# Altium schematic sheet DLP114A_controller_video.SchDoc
size 558 x 431 mm; Date: Not shown in title block; ApprovedBy: Not shown in title block; CheckedBy: Not shown in title block; Author: Not shown in title block; CompanyName: Not shown in title block; Engineer: Not shown in title block; Organization: Not shown in title block; Address1: Not shown in title block; Address2: Not shown in title block; Address3: Not shown in title block; Address4: Not shown in title block; DocumentNumber: 5; Revision: Use project parameter SCH_Rev; SheetNumber: 5; SheetTotal: 7; PageSetup: Record=PageOptions¦CenterHorizontal=True¦CenterVertical=True¦PrintScale=1.00¦XCorrection=1.00¦YCorrection=1.00¦PrintKind=0¦BorderSize=5000000¦LeftOffset=0¦BottomOffset=0¦Orientation=2¦PaperLength=1000¦PaperWidth=1000¦Scale=100¦PaperSource=15¦PrintQuality=600¦MediaType=1¦DitherType=10¦PaperKind=Letter¦PrintScaleMode=1
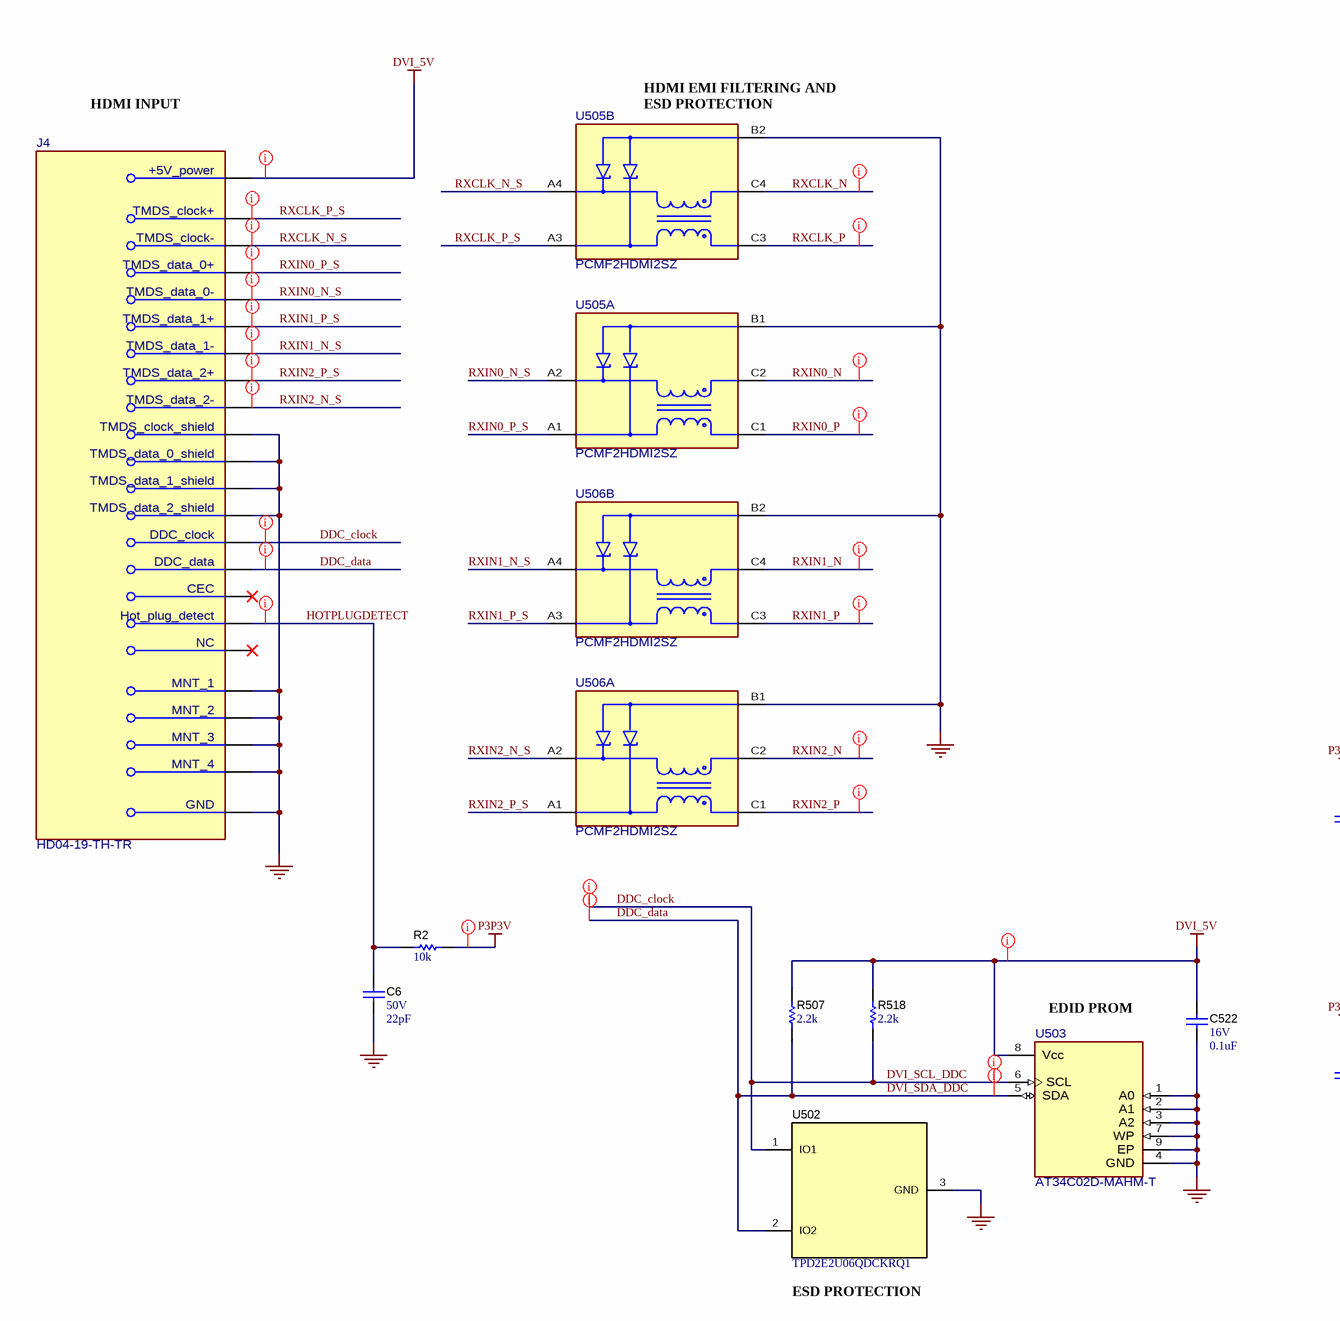
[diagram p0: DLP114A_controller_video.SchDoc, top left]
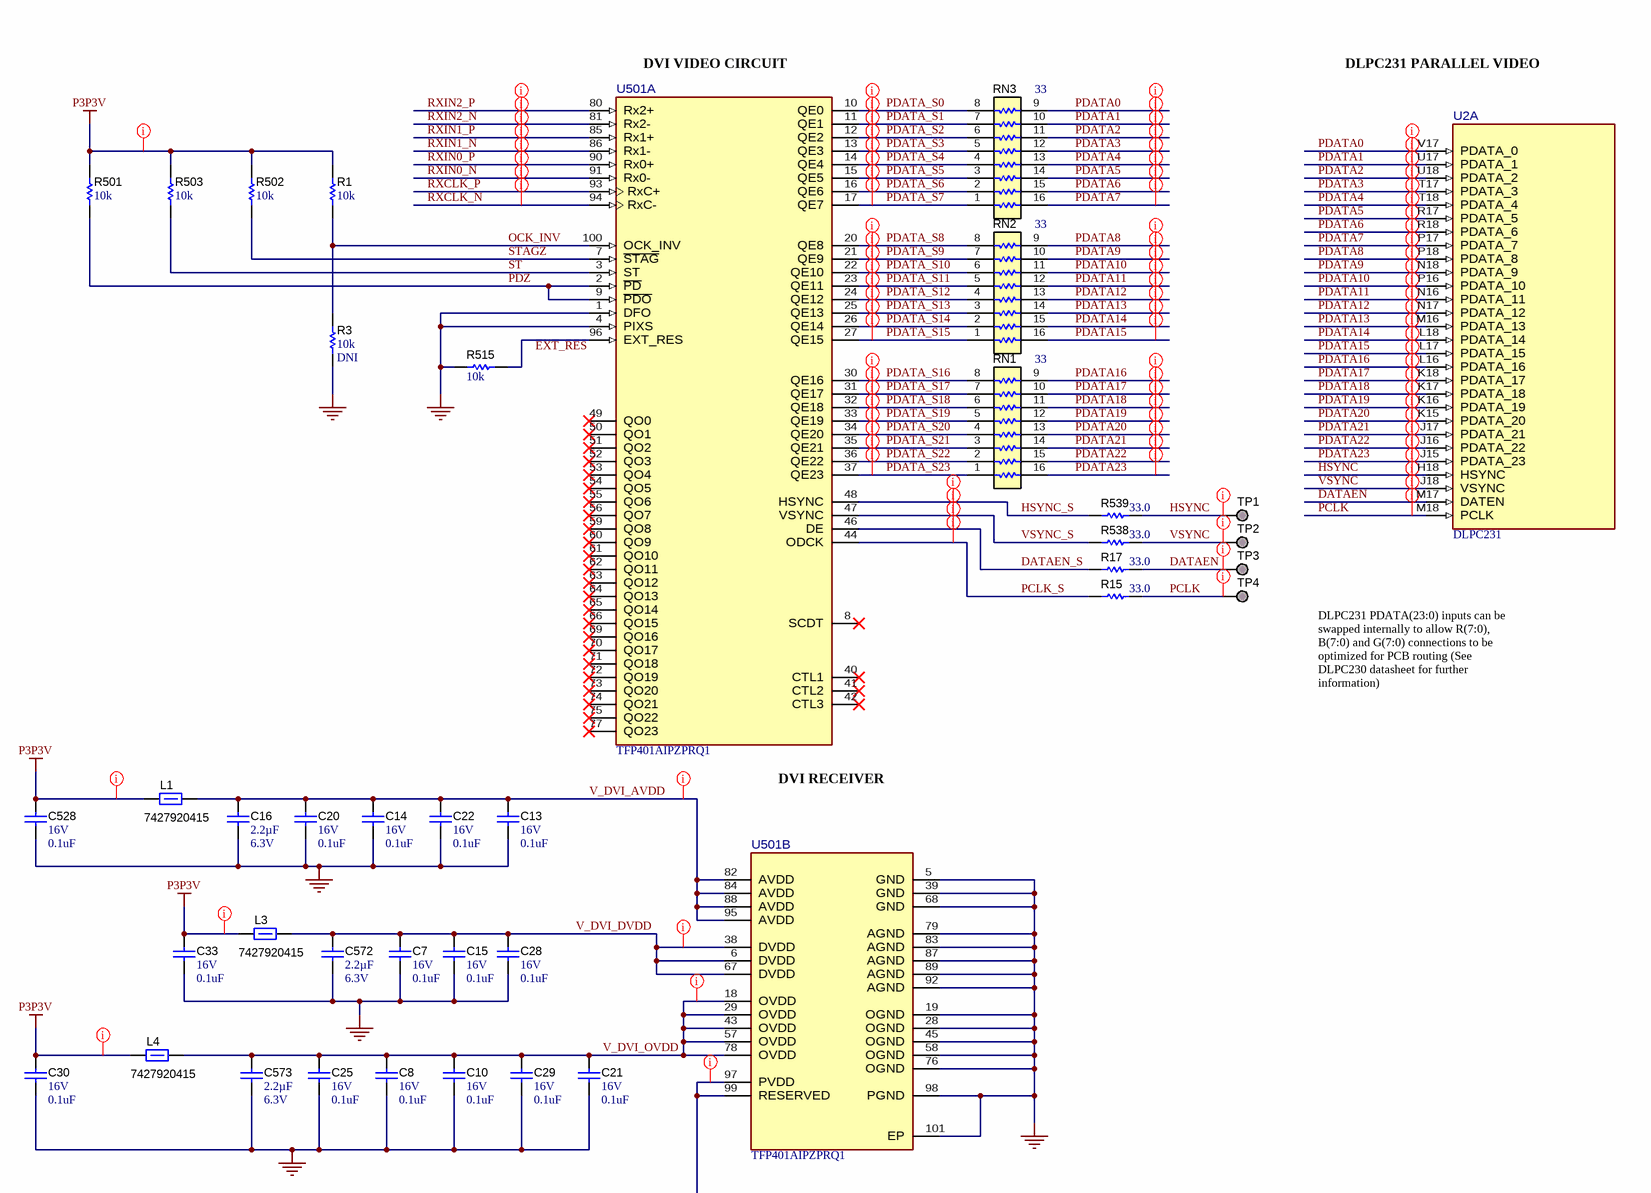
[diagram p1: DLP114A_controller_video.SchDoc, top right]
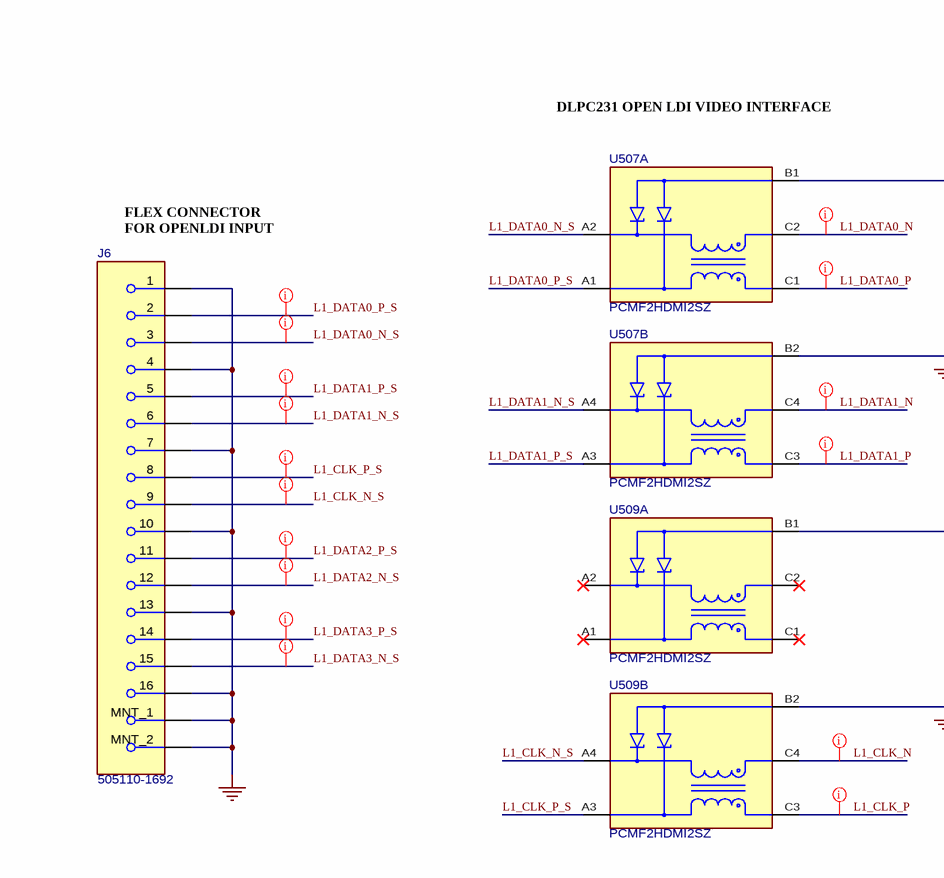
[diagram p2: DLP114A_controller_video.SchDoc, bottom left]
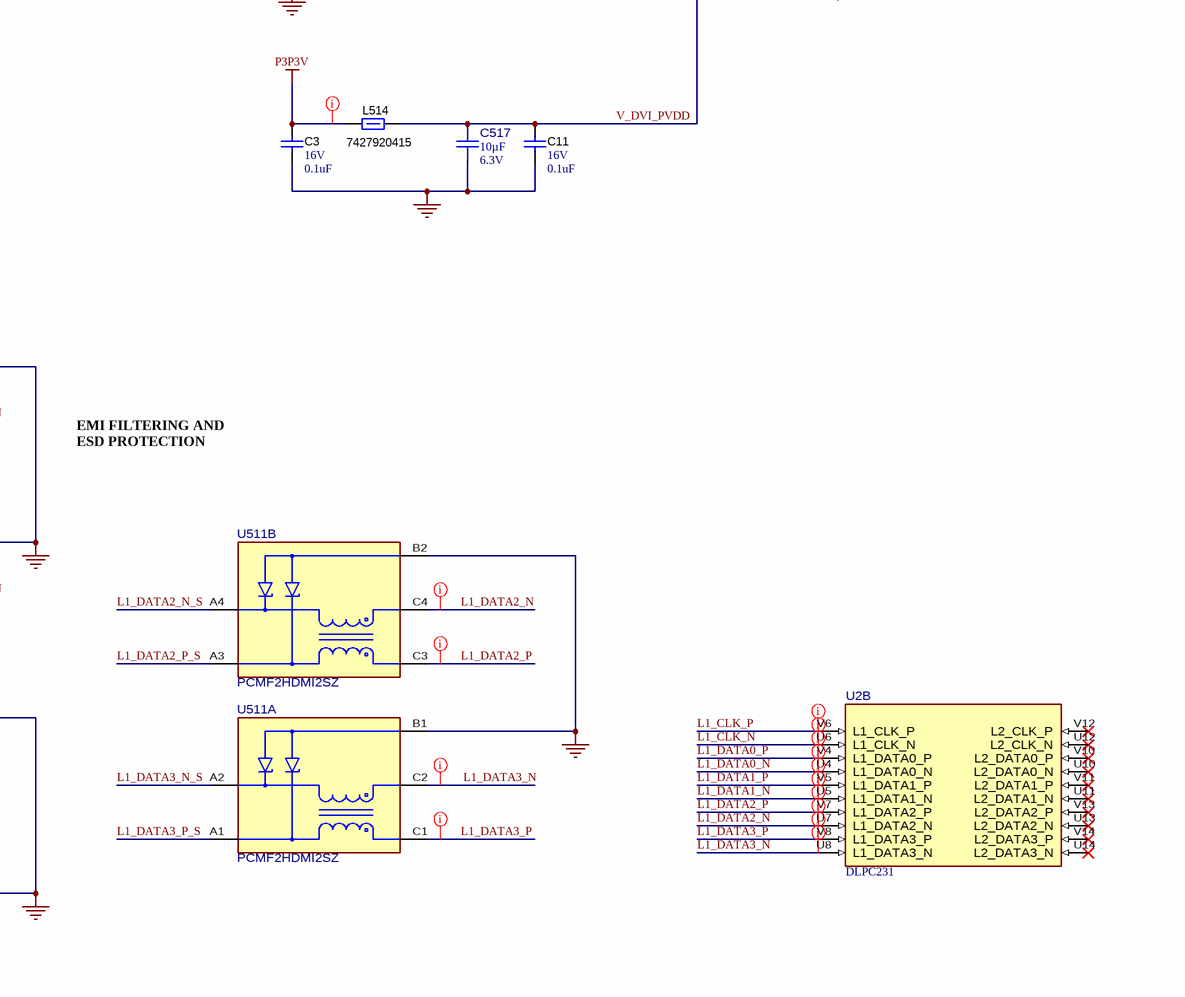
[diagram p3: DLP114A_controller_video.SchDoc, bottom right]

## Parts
C3  VDC_V: 16V  ValueDisplayed: 0.1uF  [0402]  (hidden comment: GCM155R71C104KA55D)
C6  VDC_V: 50V  ValueDisplayed: 22pF  [0402]  (hidden comment: CL05C220JB5NNNC)
C7  VDC_V: 16V  ValueDisplayed: 0.1uF  [0402]  (hidden comment: GCM155R71C104KA55D)
C8  VDC_V: 16V  ValueDisplayed: 0.1uF  [0402]  (hidden comment: GCM155R71C104KA55D)
C10  VDC_V: 16V  ValueDisplayed: 0.1uF  [0402]  (hidden comment: GCM155R71C104KA55D)
C11  VDC_V: 16V  ValueDisplayed: 0.1uF  [0402]  (hidden comment: GCM155R71C104KA55D)
C13  VDC_V: 16V  ValueDisplayed: 0.1uF  [0402]  (hidden comment: GCM155R71C104KA55D)
C14  VDC_V: 16V  ValueDisplayed: 0.1uF  [0402]  (hidden comment: GCM155R71C104KA55D)
C15  VDC_V: 16V  ValueDisplayed: 0.1uF  [0402]  (hidden comment: GCM155R71C104KA55D)
C16  Cap_F: 2.2µF  VDC_V: 6.3V  [0603]  (hidden comment: GCM188R70J225KE22D)
C20  VDC_V: 16V  ValueDisplayed: 0.1uF  [0402]  (hidden comment: GCM155R71C104KA55D)
C21  VDC_V: 16V  ValueDisplayed: 0.1uF  [0402]  (hidden comment: GCM155R71C104KA55D)
C22  VDC_V: 16V  ValueDisplayed: 0.1uF  [0402]  (hidden comment: GCM155R71C104KA55D)
C25  VDC_V: 16V  ValueDisplayed: 0.1uF  [0402]  (hidden comment: GCM155R71C104KA55D)
C28  VDC_V: 16V  ValueDisplayed: 0.1uF  [0402]  (hidden comment: GCM155R71C104KA55D)
C29  VDC_V: 16V  ValueDisplayed: 0.1uF  [0402]  (hidden comment: GCM155R71C104KA55D)
C30  VDC_V: 16V  ValueDisplayed: 0.1uF  [0402]  (hidden comment: GCM155R71C104KA55D)
C33  VDC_V: 16V  ValueDisplayed: 0.1uF  [0402]  (hidden comment: GCM155R71C104KA55D)
C517  Cap_F: 10µF  VDC_V: 6.3V  [FP-CGA4J1X7R0J106K125AC_0805-MFG]  (hidden comment: CGA4J1X7R0J106K125AC)
C522  VDC_V: 16V  ValueDisplayed: 0.1uF  [0402]  (hidden comment: GCM155R71C104KA55D)
C528  VDC_V: 16V  ValueDisplayed: 0.1uF  [0402]  (hidden comment: GCM155R71C104KA55D)
C572  Cap_F: 2.2µF  VDC_V: 6.3V  [0603]  (hidden comment: GCM188R70J225KE22D)
C573  Cap_F: 2.2µF  VDC_V: 6.3V  [0603]  (hidden comment: GCM188R70J225KE22D)
J4  HD04-19-TH-TR  [FP-HD04-19-TH-TR_CONN_HDMI_RCPT19-MFG]
J6  505110-1692  [FP-505110-1692_CONN_SMT_12MM7_5MM25-MFG]
L1  7427920415  [0805_HV]
L3  7427920415  [0805_HV]
L4  7427920415  [0805_HV]
L514  7427920415  [0805_HV]
R1  ValueDisplayed: 10k  [0402]  (hidden comment: ERJ-2GEJ103X)
R2  ValueDisplayed: 10k  [0402]  (hidden comment: ERJ-2GEJ103X)
R3  ValueDisplayed: 10k  Parameter 1: DNI  [0402]  (hidden comment: ERJ-2GEJ103X)
R15  ValueDisplayed: 33.0  [0402]  (hidden comment: ERJ-2RKF33R0X)
R17  ValueDisplayed: 33.0  [0402]  (hidden comment: ERJ-2RKF33R0X)
R501  ValueDisplayed: 10k  [0402]  (hidden comment: ERJ-2GEJ103X)
R502  ValueDisplayed: 10k  [0402]  (hidden comment: ERJ-2GEJ103X)
R503  ValueDisplayed: 10k  [0402]  (hidden comment: ERJ-2GEJ103X)
R507  ValueDisplayed: 2.2k  [0402]  (hidden comment: CRCW04022K20JNED)
R515  ValueDisplayed: 10k  [0402]  (hidden comment: ERJ-2GEJ103X)
R518  ValueDisplayed: 2.2k  [0402]  (hidden comment: CRCW04022K20JNED)
R538  ValueDisplayed: 33.0  [0402]  (hidden comment: ERJ-2RKF33R0X)
R539  ValueDisplayed: 33.0  [0402]  (hidden comment: ERJ-2RKF33R0X)
RN1  ValueDisplayed: 33  [RESCAXS_EXB-2HV]  (hidden comment: EXB-2HV330JV)
RN2  ValueDisplayed: 33  [RESCAXS_EXB-2HV]  (hidden comment: EXB-2HV330JV)
RN3  ValueDisplayed: 33  [RESCAXS_EXB-2HV]  (hidden comment: EXB-2HV330JV)
TP1  TESTPOINT  [TESTPOINT]  (value not drawn)  (no BOM)
TP2  TESTPOINT  [TESTPOINT]  (value not drawn)  (no BOM)
TP3  TESTPOINT  [TESTPOINT]  (value not drawn)  (no BOM)
TP4  TESTPOINT  [TESTPOINT]  (value not drawn)  (no BOM)
U2  DLPC231  [ZEK0324A-MFG]  (parts A,B of 9)
U501  TFP401AIPZPRQ1  [PZP0100H-MFG]  (parts A,B of 2)
U502  TPD2E2U06QDCKRQ1  [DCK0003A_N]
U503  AT34C02D-MAHM-T  [FP-AT34C02D-MAHM-T_UDFN8-MFG]
U505  PCMF2HDMI2SZ  [FP-PCMF2HDMI2SZ_WLCSP10-MFG]  (parts A,B of 2)
U506  PCMF2HDMI2SZ  [FP-PCMF2HDMI2SZ_WLCSP10-MFG]  (parts A,B of 2)
U507  PCMF2HDMI2SZ  [FP-PCMF2HDMI2SZ_WLCSP10-MFG]  (parts A,B of 2)
U509  PCMF2HDMI2SZ  [FP-PCMF2HDMI2SZ_WLCSP10-MFG]  (parts A,B of 2)
U511  PCMF2HDMI2SZ  [FP-PCMF2HDMI2SZ_WLCSP10-MFG]  (parts A,B of 2)

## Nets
DVI_5V: C522.1 J4.18(+5V_power) R507.2 R518.2 U503.8(Vcc)
GND: C3.2 C6.2 C7.2 C8.2 C10.2 C11.2 C13.2 C14.2 C15.2 C16.2 C20.2 C21.2 C22.2 C25.2 C28.2 C29.2 C30.2 C33.2 C517.1 C522.2 C528.2 C572.2 C573.2 J4.2(TMDS_data_2_shield) J4.5(TMDS_data_1_shield) J4.8(TMDS_data_0_shield) J4.11(TMDS_clock_shield) J4.17(GND) J4.20(MNT_1) J4.21(MNT_2) J4.22(MNT_3) J4.23(MNT_4) J6.1 J6.4 J6.7 J6.10 J6.13 J6.16 J6.17(MNT_1) J6.18(MNT_2) R3.1 R515.2 U501.1(DFO) U501.4(PIXS) U501.5(GND) U501.19(OGND) U501.28(OGND) U501.39(GND) U501.45(OGND) U501.58(OGND) U501.68(GND) U501.76(OGND) U501.79(AGND) U501.83(AGND) U501.87(AGND) U501.89(AGND) U501.92(AGND) U501.98(PGND) U501.101(EP) U502.3(GND) U503.1(A0) U503.2(A1) U503.3(A2) U503.4(GND) U503.7(WP) U503.9(EP) U505.B1(GND_CH1) U505.B2(GND_CH2) U506.B1(GND_CH1) U506.B2(GND_CH2) U507.B1(GND_CH1) U507.B2(GND_CH2) U509.B1(GND_CH1) U509.B2(GND_CH2) U511.B1(GND_CH1) U511.B2(GND_CH2)
P3P3V: C3.1 C30.1 C33.1 C528.1 L1.1 L3.1 L4.1 L514.1 R1.2 R2.2 R501.2 R502.2 R503.2
DATAEN: R17.2 TP3.1 U2.M17(DATEN)
DATAEN_S: R17.1 U501.46(DE)
DDC_clock: J4.15(DDC_clock) R518.1 U502.1(IO1) U503.6(SCL)  [also labelled DVI_SCL_DDC]
DDC_data: J4.16(DDC_data) R507.1 U502.2(IO2) U503.5(SDA)  [also labelled DVI_SDA_DDC]
HOTPLUGDETECT: C6.1 J4.19(Hot_plug_detect) R2.1
HSYNC: R539.2 TP1.1 U2.H18(HSYNC)
HSYNC_S: R539.1 U501.48(HSYNC)
L1_CLK_N: U2.U6(L1_CLK_N) U509.C4(CH2_OUT-)
L1_CLK_N_S: J6.9 U509.A4(CH2_IN-)
L1_CLK_P: U2.V6(L1_CLK_P) U509.C3(CH2_OUT+)
L1_CLK_P_S: J6.8 U509.A3(CH2_IN+)
L1_DATA0_N: U2.U4(L1_DATA0_N) U507.C2(CH1_OUT-)
L1_DATA0_N_S: J6.3 U507.A2(CH1_IN-)
L1_DATA0_P: U2.V4(L1_DATA0_P) U507.C1(CH1_OUT+)
L1_DATA0_P_S: J6.2 U507.A1(CH1_IN+)
L1_DATA1_N: U2.U5(L1_DATA1_N) U507.C4(CH2_OUT-)
L1_DATA1_N_S: J6.6 U507.A4(CH2_IN-)
L1_DATA1_P: U2.V5(L1_DATA1_P) U507.C3(CH2_OUT+)
L1_DATA1_P_S: J6.5 U507.A3(CH2_IN+)
L1_DATA2_N: U2.U7(L1_DATA2_N) U511.C4(CH2_OUT-)
L1_DATA2_N_S: J6.12 U511.A4(CH2_IN-)
L1_DATA2_P: U2.V7(L1_DATA2_P) U511.C3(CH2_OUT+)
L1_DATA2_P_S: J6.11 U511.A3(CH2_IN+)
L1_DATA3_N: U2.U8(L1_DATA3_N) U511.C2(CH1_OUT-)
L1_DATA3_N_S: J6.15 U511.A2(CH1_IN-)
L1_DATA3_P: U2.V8(L1_DATA3_P) U511.C1(CH1_OUT+)
L1_DATA3_P_S: J6.14 U511.A1(CH1_IN+)
OCK_INV: R1.1 R3.2 U501.100(OCK_INV)
PCLK: R15.2 TP4.1 U2.M18(PCLK)
PCLK_S: R15.1 U501.44(ODCK)
PDATA0: RN3.9 U2.V17(PDATA_0)
PDATA1: RN3.10 U2.U17(PDATA_1)
PDATA2: RN3.11 U2.U18(PDATA_2)
PDATA3: RN3.12 U2.T17(PDATA_3)
PDATA4: RN3.13 U2.T18(PDATA_4)
PDATA5: RN3.14 U2.R17(PDATA_5)
PDATA6: RN3.15 U2.R18(PDATA_6)
PDATA7: RN3.16 U2.P17(PDATA_7)
PDATA8: RN2.9 U2.P18(PDATA_8)
PDATA9: RN2.10 U2.N18(PDATA_9)
PDATA10: RN2.11 U2.P16(PDATA_10)
PDATA11: RN2.12 U2.N16(PDATA_11)
PDATA12: RN2.13 U2.N17(PDATA_12)
PDATA13: RN2.14 U2.M16(PDATA_13)
PDATA14: RN2.15 U2.L18(PDATA_14)
PDATA15: RN2.16 U2.L17(PDATA_15)
PDATA16: RN1.9 U2.L16(PDATA_16)
PDATA17: RN1.10 U2.K18(PDATA_17)
PDATA18: RN1.11 U2.K17(PDATA_18)
PDATA19: RN1.12 U2.K16(PDATA_19)
PDATA20: RN1.13 U2.K15(PDATA_20)
PDATA21: RN1.14 U2.J17(PDATA_21)
PDATA22: RN1.15 U2.J16(PDATA_22)
PDATA23: RN1.16 U2.J15(PDATA_23)
PDATA_S0: RN3.8 U501.10(QE0)
PDATA_S1: RN3.7 U501.11(QE1)
PDATA_S2: RN3.6 U501.12(QE2)
PDATA_S3: RN3.5 U501.13(QE3)
PDATA_S4: RN3.4 U501.14(QE4)
PDATA_S5: RN3.3 U501.15(QE5)
PDATA_S6: RN3.2 U501.16(QE6)
PDATA_S7: RN3.1 U501.17(QE7)
PDATA_S8: RN2.8 U501.20(QE8)
PDATA_S9: RN2.7 U501.21(QE9)
PDATA_S10: RN2.6 U501.22(QE10)
PDATA_S11: RN2.5 U501.23(QE11)
PDATA_S12: RN2.4 U501.24(QE12)
PDATA_S13: RN2.3 U501.25(QE13)
PDATA_S14: RN2.2 U501.26(QE14)
PDATA_S15: RN2.1 U501.27(QE15)
PDATA_S16: RN1.8 U501.30(QE16)
PDATA_S17: RN1.7 U501.31(QE17)
PDATA_S18: RN1.6 U501.32(QE18)
PDATA_S19: RN1.5 U501.33(QE19)
PDATA_S20: RN1.4 U501.34(QE20)
PDATA_S21: RN1.3 U501.35(QE21)
PDATA_S22: RN1.2 U501.36(QE22)
PDATA_S23: RN1.1 U501.37(QE23)
PDZ: R501.1 U501.2(~{PD}) U501.9(~{PDO})
RXCLK_N: U501.94(RxC-) U505.C4(CH2_OUT-)
RXCLK_N_S: J4.12(TMDS_clock-) U505.A4(CH2_IN-)
RXCLK_P: U501.93(RxC+) U505.C3(CH2_OUT+)
RXCLK_P_S: J4.10(TMDS_clock+) U505.A3(CH2_IN+)
RXIN0_N: U501.91(Rx0-) U505.C2(CH1_OUT-)
RXIN0_N_S: J4.9(TMDS_data_0-) U505.A2(CH1_IN-)
RXIN0_P: U501.90(Rx0+) U505.C1(CH1_OUT+)
RXIN0_P_S: J4.7(TMDS_data_0+) U505.A1(CH1_IN+)
RXIN1_N: U501.86(Rx1-) U506.C4(CH2_OUT-)
RXIN1_N_S: J4.6(TMDS_data_1-) U506.A4(CH2_IN-)
RXIN1_P: U501.85(Rx1+) U506.C3(CH2_OUT+)
RXIN1_P_S: J4.4(TMDS_data_1+) U506.A3(CH2_IN+)
RXIN2_N: U501.81(Rx2-) U506.C2(CH1_OUT-)
RXIN2_N_S: J4.3(TMDS_data_2-) U506.A2(CH1_IN-)
RXIN2_P: U501.80(Rx2+) U506.C1(CH1_OUT+)
RXIN2_P_S: J4.1(TMDS_data_2+) U506.A1(CH1_IN+)
ST: R503.1 U501.3(ST)
STAGZ: R502.1 U501.7(~{STAG})
V_DVI_AVDD: C13.1 C14.1 C16.1 C20.1 C22.1 L1.2 U501.82(AVDD) U501.84(AVDD) U501.88(AVDD) U501.95(AVDD)
V_DVI_DVDD: C7.1 C15.1 C28.1 C572.1 L3.2 U501.6(DVDD) U501.38(DVDD) U501.67(DVDD)
V_DVI_OVDD: C8.1 C10.1 C21.1 C25.1 C29.1 C573.1 L4.2 U501.18(OVDD) U501.29(OVDD) U501.43(OVDD) U501.57(OVDD) U501.78(OVDD)
V_DVI_PVDD: C11.1 C517.2 L514.2 U501.97(PVDD) U501.99(RESERVED)
VSYNC: R538.2 TP2.1 U2.J18(VSYNC)
VSYNC_S: R538.1 U501.47(VSYNC)
NetR515_1: R515.1 U501.96(EXT_RES)

Not connected (* = marked no-connect by the designer): J4 13(CEC)* 14(NC)*; U2 U10(L2_DATA0_N)* U11(L2_DATA1_N)* U12(L2_CLK_N)* U13(L2_DATA2_N)* U14(L2_DATA3_N)* V10(L2_DATA0_P)* V11(L2_DATA1_P)* V12(L2_CLK_P)* V13(L2_DATA2_P)* V14(L2_DATA3_P)*; U501 8(SCDT)* 40(CTL1)* 41(CTL2)* 42(CTL3)* 49(QO0)* 50(QO1)* 51(QO2)* 52(QO3)* 53(QO4)* 54(QO5)* 55(QO6)* 56(QO7)* 59(QO8)* 60(QO9)* 61(QO10)* 62(QO11)* 63(QO12)* 64(QO13)* 65(QO14)* 66(QO15)* 69(QO16)* 70(QO17)* 71(QO18)* 72(QO19)* 73(QO20)* 74(QO21)* 75(QO22)* 77(QO23)*; U509 A1(CH1_IN+)* A2(CH1_IN-)* C1(CH1_OUT+)* C2(CH1_OUT-)*

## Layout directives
net class 100 OHM (HDMI Signals): RXCLK_N, RXCLK_N_S, RXCLK_P, RXCLK_P_S, RXIN0_N, RXIN0_N_S, RXIN0_P, RXIN0_P_S, RXIN1_N, RXIN1_N_S, RXIN1_P, RXIN1_P_S, RXIN2_N, RXIN2_N_S, RXIN2_P, RXIN2_P_S
net class 50OHM: DATAEN, DATAEN_S, DDC_clock, DDC_data, HOTPLUGDETECT, HSYNC, HSYNC_S, L1_CLK_N, L1_CLK_P, L1_DATA0_N, L1_DATA0_P, L1_DATA1_N, L1_DATA1_P, L1_DATA2_N, L1_DATA2_P, L1_DATA3_N, L1_DATA3_P, PCLK, PCLK_S, PDATA0, PDATA1, PDATA2, PDATA3, PDATA4, PDATA5, PDATA6, PDATA7, PDATA8, PDATA9, PDATA10, PDATA11, PDATA12, PDATA13, PDATA14, PDATA15, PDATA16, PDATA17, PDATA18, PDATA19, PDATA20, PDATA21, PDATA22, PDATA23, PDATA_S0, PDATA_S1, PDATA_S2, PDATA_S3, PDATA_S4, PDATA_S5, PDATA_S6, PDATA_S7, PDATA_S8, PDATA_S9, PDATA_S10, PDATA_S11, PDATA_S12, PDATA_S13, PDATA_S14, PDATA_S15, PDATA_S16, PDATA_S17, PDATA_S18, PDATA_S19, PDATA_S20, PDATA_S21, PDATA_S22, PDATA_S23, VSYNC, VSYNC_S
net class 100 OHM (Open LDI): L1_CLK_N, L1_CLK_N_S, L1_CLK_P, L1_CLK_P_S, L1_DATA0_N, L1_DATA0_N_S, L1_DATA0_P, L1_DATA0_P_S, L1_DATA1_N, L1_DATA1_N_S, L1_DATA1_P, L1_DATA1_P_S, L1_DATA2_N, L1_DATA2_N_S, L1_DATA2_P, L1_DATA2_P_S, L1_DATA3_N, L1_DATA3_N_S, L1_DATA3_P, L1_DATA3_P_S
net class POWER: DVI_5V, P3P3V, V_DVI_AVDD, V_DVI_DVDD, V_DVI_OVDD, V_DVI_PVDD

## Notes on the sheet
- HDMI INPUT
- (near U505) HDMI EMI FILTERING AND
  ESD PROTECTION
- (near U501) DVI VIDEO CIRCUIT
- DLPC231 PARALLEL VIDEO INTERFACE
- DLPC231 PDATA(23:0) inputs can be
  swapped internally to allow R(7:0),
  B(7:0) and G(7:0) connections to be
  optimized for PCB routing (See
  DLPC230 datasheet for further
  information)
- (near U501) DVI RECEIVER
- EDID PROM
- (near U502) ESD PROTECTION
- DLPC231 OPEN LDI VIDEO INTERFACE
- FLEX CONNECTOR
  FOR OPENLDI INPUT
- EMI FILTERING AND
  ESD PROTECTION
- Labels drawn without touching a wire or pin: EXT_RES

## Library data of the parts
C3 C7 C8 C10 C11 C13-C15 C20-C22 C25 C28-C30 C33 C522 C528 = CMP-0006351-2: CAP, CERM, 0.1 uF, 16 V, +/- 10%, X7R, 0402; Manufacturer: MuRata; TaMin_C: -55°C; Polarized: N; SizeAreaWB_mm2: 3; Value1: Unknown; U/M: EA; Value: 0.1uF; TaMax_C: 125°C; SizeZ_mm: 0.6; SizeX_mm: 1; SizeY_mm: 0.5; Cap_F: 100nF; AEC Category: Q200
C6 = CMP-0085851-1: CAP, CERM, 22 pF, 50 V,+/- 5%, C0G/NP0, 0402; Manufacturer: Walsin; AEC Qualified: N; TaMax_C: 125°C; SizeX_mm: 1; Value: 22pF; SizeZ_mm: 0.6; AEC Category: Q200; TaMin_C: -55°C; SizeArea_mm2: 0.5; SizeAreaWB_mm2: 3; U/M: EA
C16 C572 C573 = CMP-0007134-5: CAP, CERM, 2.2 uF, 6.3 V, +/- 10%, X7R, AEC-Q200 Grade 1, 0603; Manufacturer: MuRata; TaMin_C: -55°C; Polarized: N; SizeAreaWB_mm2: 4.68; Value1: Unknown; U/M: EA; Value: 2.2uF; TaMax_C: 125°C; SizeZ_mm: 1; SizeX_mm: 1.6; SizeY_mm: 0.8; SizeArea_mm2: 1.28; AEC Qualified: Y; AEC Category: Q200
C517 = CMP-0093813-1: Cap Ceramic 10uF 6.3V X7R 10% Pad SMD 0805 +125°C Automotive T/R; Manufacturer: TDK Corporation; Value: 10µF; TempCo: 15%; AEC Qualified: Yes; AEC Grade: Grade 1; Tolerance_%: 0.1%; SizeZ_mm: 1.45mm
J4 = CMP-0095855-1: HDMI 2.1 Receptacle Connector 19 Position Surface Mount, Right Angle; Through Hole; Manufacturer: CUI Devices; DUT-Pitch_mm: 0.5mm; Conn Orientation: Horizontal; Current_A: 500mA; SizeZ_mm: 6.27mm; Is Female: yes; ContactFinish: Gold; Voltage_V: 40V; AEC Qualified: No
J6 = CMP-0086503-1: CONN FPC BOTTOM 16POS .5MM R/A; Manufacturer: Molex; Voltage_V: 50V; Current_A: 0.5A; ContactFinish: Gold,Nickel
L1 L3 L4 L514 = CMP-0003086-1: Ferrite Bead, 600 ohm @ 100 MHz, 0.5 A, 0805; Manufacturer: Wurth Elektronik; Ztyp@1GHz_Ohm: 141.542; ZTyp@100MHz_Ohm: 600; SizeAreaWB_mm2: 6.75; DCR_ohm: 0.3; Value1: 0.3 ohm; Value: 600 ohm; Imax_A: 500mA; SizeZ_mm: 1.45; SizeX_mm: 2; SizeY_mm: 1.25; Value2: 0.5A; SizeArea_mm2: 2.5
R1-R3 R501-R503 R515 = CMP-0026994-4: RES, 10 k, 5%, 0.1 W, AEC-Q200 Grade 0, 0402; Manufacturer: Panasonic; Power_W: 100mW; TempCo: 200 ppm/C; Value_Code: 10k0; U/M: EA; Value: 10k; EIA_Code: E24; SizeX_mm: 1; SizeY_mm: 0.5; SizeZ_mm: 0.6; Value2: 0.1W; AEC Qualified: Y; VDC_V: 50V; AEC Grade: 0; AEC Category: Q200
R15 R17 R538 R539 = CMP-0026696-1: RES, 33.0, 1%, 0.1 W, 0402; Manufacturer: Panasonic; Power_W: 100mW; TempCo: 100 ppm/C; Value_Code: 33R0; U/M: EA; Value: 33.0; Res_ohm: 33; SizeX_mm: 1; SizeY_mm: 0.5; SizeZ_mm: 0.6; Value2: 0.1W; VDC_V: 50V; AEC Category: Q200
R507 R518 = CMP-0026890-5: RES, 2.2 k, 5%, 0.063 W, AEC-Q200 Grade 0, 0402; Manufacturer: Vishay-Dale; Power_W: 63mW; TempCo: 200 ppm/C; Value_Code: 2k20; Value: 2.2k; EIA_Code: E24; SizeX_mm: 1; SizeY_mm: 0.5; SizeZ_mm: 0.6; Value2: 0.063W; AEC Qualified: Y; VDC_V: 50V; AEC Category: Q200; AEC Grade: 0
RN1-RN3 = CMP-0015347-2: RES, 33, 5%, 0.0625 W, Resistor Array - 8x1; Manufacturer: Panasonic; Power_W: 62.5mW; TempCo: 200 ppm/C; Value_Code: 33R0; U/M: EA; Value: 33; EIA_Code: E24; AEC Category: Q200
TP1-TP4 = CMP-0078143-2: TEST POINT.  No entry in BOM.
U2 = CMP-0096130-1: Manufacturer: Texas Instruments; Standoff Height: 0.35mm; SizeZ_mm: 1.5mm
U501 = CMP-0095606-2: Digital Receiver 3RX 100-Pin HTQFP EP T/R; Manufacturer: Texas Instruments; SizeZ_mm: 1.2mm; AEC Qualified: Yes; AEC Grade: Grade 3; TaMax_C: +85°C; Standoff Height: 0.05mm; CompType: IC; Min Supply Voltage: 3V; Max Supply Voltage: 3.6V; AEC Category: Q200; TaMin_C: -40°C; Interface: Other
U502 = CMP-0073595-1: Automotive Dual-Channel High-Speed ESD Protection Device, DCK0003A (SOT-SC70-3); Alternate Manufacturer: Texas Instruments; SizeAreaWB_mm2: 9.3; U/M: EA; SizeZ_mm: 1.1; SizeX_mm: 2.1; SizeY_mm: 2.0; SizeArea_mm2: 4.2; CompType: IC
U503 = CMP-0095877-1: EEPROM Memory IC 2Kb (256 x 8) I²C 1 MHz 8-UDFN (2x3); Manufacturer: Microchip Technology; Memory Size: 2Kbits; Min Supply Voltage: 1.7V; AEC Qualified: No; Max Supply Voltage: 5.5V; Standoff Height: 0mm; SizeZ_mm: 0.6mm; Interface: I2C; Nominal Supply Current: 1-2mA; Frequency_Fixed: 1MHz
U505-U507 U509 U511 = CMP-0095720-1: Common-mode EMI filter for differential channels with ESD protection; Manufacturer: Nexperia; TaMin_C: -40°C; Standoff Height: 0.16mm; TaMax_C: +85°C; SizeZ_mm: 0.6mm; DCR_ohm: 3Ω; AEC Qualified: No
